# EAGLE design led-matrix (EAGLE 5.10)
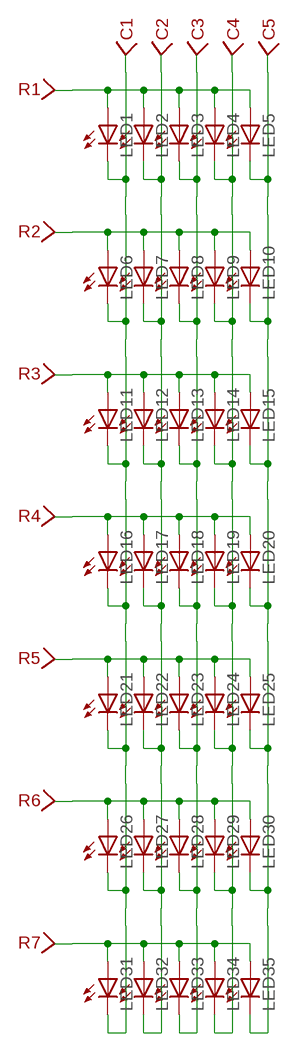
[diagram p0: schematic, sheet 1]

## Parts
C1  WIREPAD-SMD-SMALL-NAMED  [WIREPAD-SMD-SMALL]
C2  WIREPAD-SMD-SMALL-NAMED  [WIREPAD-SMD-SMALL]
C3  WIREPAD-SMD-SMALL-NAMED  [WIREPAD-SMD-SMALL]
C4  WIREPAD-SMD-SMALL-NAMED  [WIREPAD-SMD-SMALL]
C5  WIREPAD-SMD-SMALL-NAMED  [WIREPAD-SMD-SMALL]
LED1  LEDCHIPLED_0805  [CHIPLED_0805]
LED2  LEDCHIPLED_0805  [CHIPLED_0805]
LED3  LEDCHIPLED_0805  [CHIPLED_0805]
LED4  LEDCHIPLED_0805  [CHIPLED_0805]
LED5  LEDCHIPLED_0805  [CHIPLED_0805]
LED6  LEDCHIPLED_0805  [CHIPLED_0805]
LED7  LEDCHIPLED_0805  [CHIPLED_0805]
LED8  LEDCHIPLED_0805  [CHIPLED_0805]
LED9  LEDCHIPLED_0805  [CHIPLED_0805]
LED10  LEDCHIPLED_0805  [CHIPLED_0805]
LED11  LEDCHIPLED_0805  [CHIPLED_0805]
LED12  LEDCHIPLED_0805  [CHIPLED_0805]
LED13  LEDCHIPLED_0805  [CHIPLED_0805]
LED14  LEDCHIPLED_0805  [CHIPLED_0805]
LED15  LEDCHIPLED_0805  [CHIPLED_0805]
LED16  LEDCHIPLED_0805  [CHIPLED_0805]
LED17  LEDCHIPLED_0805  [CHIPLED_0805]
LED18  LEDCHIPLED_0805  [CHIPLED_0805]
LED19  LEDCHIPLED_0805  [CHIPLED_0805]
LED20  LEDCHIPLED_0805  [CHIPLED_0805]
LED21  LEDCHIPLED_0805  [CHIPLED_0805]
LED22  LEDCHIPLED_0805  [CHIPLED_0805]
LED23  LEDCHIPLED_0805  [CHIPLED_0805]
LED24  LEDCHIPLED_0805  [CHIPLED_0805]
LED25  LEDCHIPLED_0805  [CHIPLED_0805]
LED26  LEDCHIPLED_0805  [CHIPLED_0805]
LED27  LEDCHIPLED_0805  [CHIPLED_0805]
LED28  LEDCHIPLED_0805  [CHIPLED_0805]
LED29  LEDCHIPLED_0805  [CHIPLED_0805]
LED30  LEDCHIPLED_0805  [CHIPLED_0805]
LED31  LEDCHIPLED_0805  [CHIPLED_0805]
LED32  LEDCHIPLED_0805  [CHIPLED_0805]
LED33  LEDCHIPLED_0805  [CHIPLED_0805]
LED34  LEDCHIPLED_0805  [CHIPLED_0805]
LED35  LEDCHIPLED_0805  [CHIPLED_0805]
R1  WIREPAD-SMD-SMALL-NAMED  [WIREPAD-SMD-SMALL]
R2  WIREPAD-SMD-SMALL-NAMED  [WIREPAD-SMD-SMALL]
R3  WIREPAD-SMD-SMALL-NAMED  [WIREPAD-SMD-SMALL]
R4  WIREPAD-SMD-SMALL-NAMED  [WIREPAD-SMD-SMALL]
R5  WIREPAD-SMD-SMALL-NAMED  [WIREPAD-SMD-SMALL]
R6  WIREPAD-SMD-SMALL-NAMED  [WIREPAD-SMD-SMALL]
R7  WIREPAD-SMD-SMALL-NAMED  [WIREPAD-SMD-SMALL]

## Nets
A1: LED6.A LED7.A LED8.A LED9.A LED10.A R2.1
A2: LED11.A LED12.A LED13.A LED14.A LED15.A R3.1
A3: LED16.A LED17.A LED18.A LED19.A LED20.A R4.1
A4: LED1.A LED2.A LED3.A LED4.A LED5.A R1.1
A5: LED21.A LED22.A LED23.A LED24.A LED25.A R5.1
A6: LED26.A LED27.A LED28.A LED29.A LED30.A R6.1
A7: LED31.A LED32.A LED33.A LED34.A LED35.A R7.1
C7: C5.1 LED5.C LED10.C LED15.C LED20.C LED25.C LED30.C LED35.C
N$25: C1.1 LED1.C LED6.C LED11.C LED16.C LED21.C LED26.C LED31.C
N$26: C2.1 LED2.C LED7.C LED12.C LED17.C LED22.C LED27.C LED32.C
N$27: C3.1 LED3.C LED8.C LED13.C LED18.C LED23.C LED28.C LED33.C
N$28: C4.1 LED4.C LED9.C LED14.C LED19.C LED24.C LED29.C LED34.C

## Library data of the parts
C1-C5 R1-R7 = trl:WIREPAD-SMD-SMALL-NAMED
LED1-LED35 = led:LED: LED

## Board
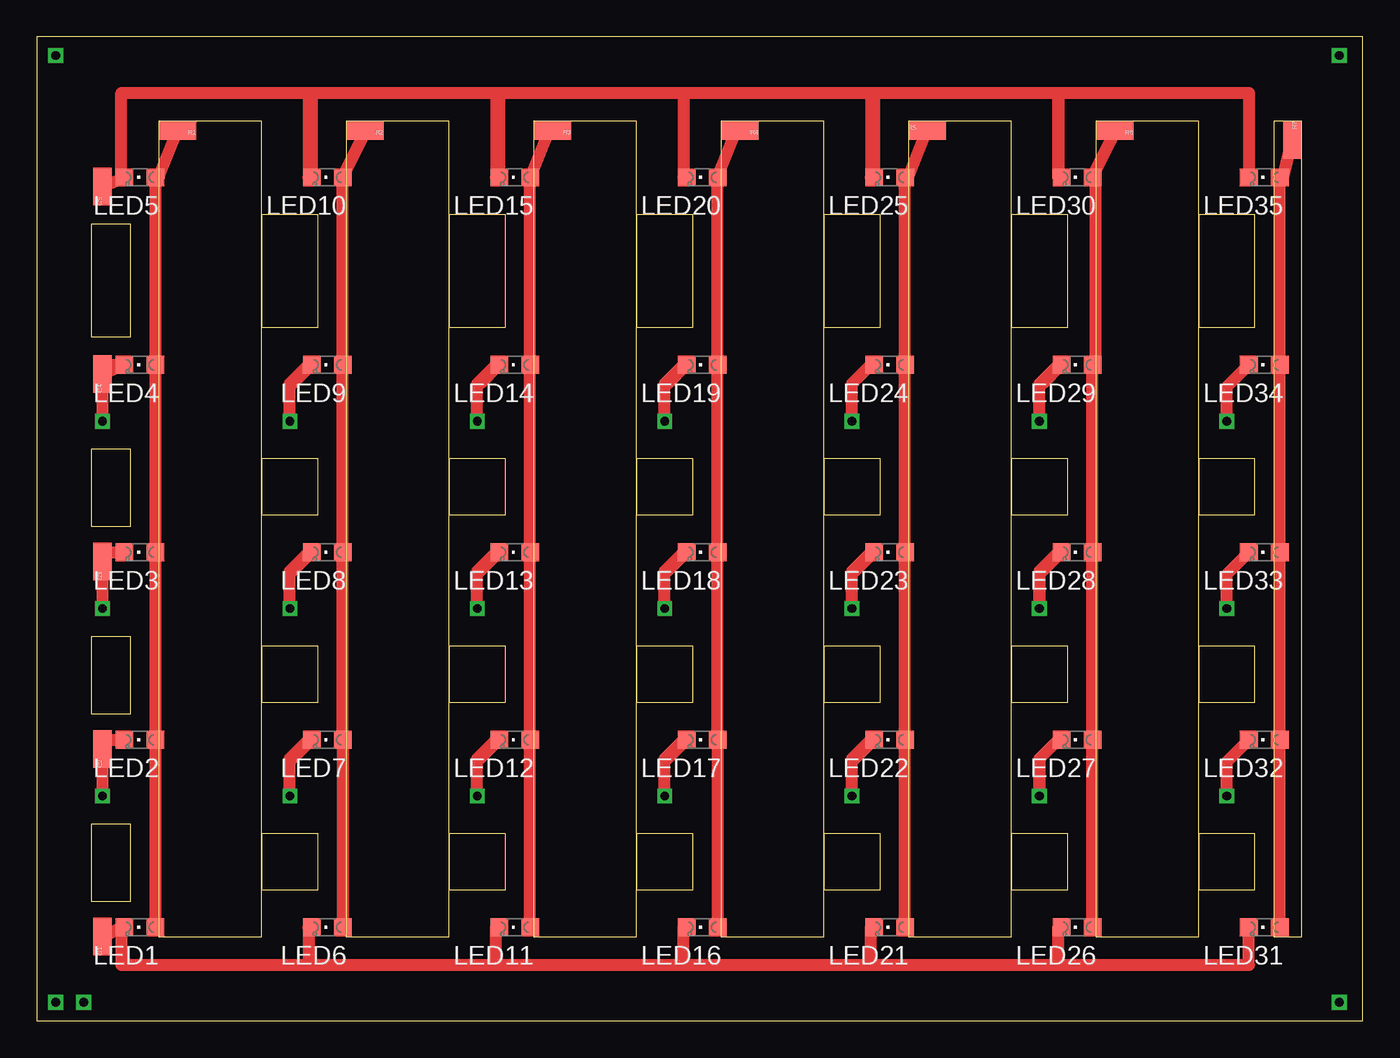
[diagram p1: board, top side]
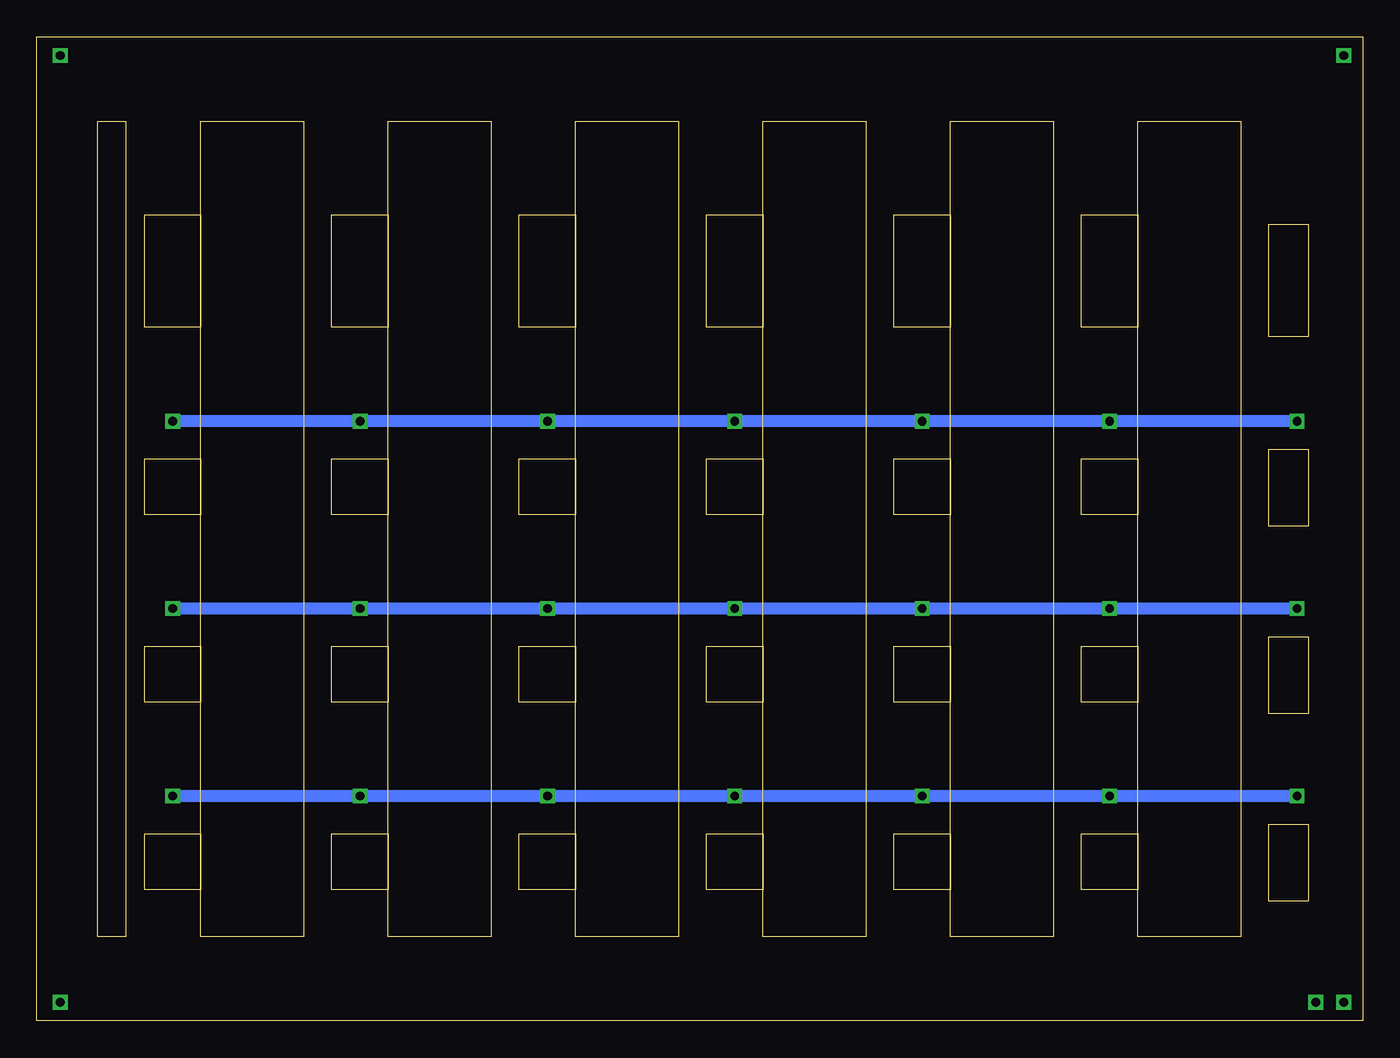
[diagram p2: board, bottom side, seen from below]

Size 89.84 x 66.67 mm. Coordinates in mm from the lower left corner, seen from the top.
Outline: 0,0 89.84,0 89.84,66.67 0,66.67 0,0
Copper layers (1*16): Top 0.035mm / dielectric 1.5mm / Bottom 0.035mm
Design rules "default": minimum track width 10mil, minimum drill 24mil, track to track 8mil, track to pad 8mil, pad to pad 8mil, via to via 8mil, smd to smd 8mil, copper to edge 40mil, drill to drill 8mil, minimum pad ring 10mil, minimum via ring 8mil, stop-mask expansion 4mil, vias tented up to drill 0mil, thermal gap 10mil
Milling: area 8.3,5.7 to 15.2,61; area 21,5.7 to 27.9,61; area 33.7,5.7 to 40.6,61; area 46.4,5.7 to 53.3,61; area 59.1,5.7 to 66,61; area 71.8,5.7 to 78.7,61; area 15.2,47 to 19.1,54.6; area 27.9,47 to 31.8,54.6; area 40.6,47 to 44.5,54.6; area 53.3,47 to 57.2,54.6; area 66,47 to 69.8,54.6; area 78.7,47 to 82.5,54.6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

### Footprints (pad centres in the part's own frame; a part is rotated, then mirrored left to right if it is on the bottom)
WIREPAD-SMD-SMALL = smd 2.54 x 1.27: 1 0,0
CHIPLED_0805 = smd 1.2 x 1.2: A 0,-1.05; C 0,1.05

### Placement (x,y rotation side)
C1  4.45,5.71 90 top
C2  4.45,18.41 90 top
C3  4.45,31.11 90 top
C4  4.45,43.81 90 top
C5  4.45,56.52 90 top
LED1  6.99,6.35 90 top
LED2  6.99,19.05 90 top
LED3  6.99,31.75 90 top
LED4  6.99,44.45 90 top
LED5  6.99,57.15 90 top
LED6  19.68,6.35 90 top
LED7  19.68,19.05 90 top
LED8  19.68,31.75 90 top
LED9  19.68,44.45 90 top
LED10  19.68,57.15 90 top
LED11  32.38,6.35 90 top
LED12  32.38,19.05 90 top
LED13  32.38,31.75 90 top
LED14  32.38,44.45 90 top
LED15  32.38,57.15 90 top
LED16  45.09,6.35 90 top
LED17  45.09,19.05 90 top
LED18  45.09,31.75 90 top
LED19  45.09,44.45 90 top
LED20  45.09,57.15 90 top
LED21  57.78,6.35 90 top
LED22  57.78,19.05 90 top
LED23  57.78,31.75 90 top
LED24  57.78,44.45 90 top
LED25  57.78,57.15 90 top
LED26  70.48,6.35 90 top
LED27  70.48,19.05 90 top
LED28  70.48,31.75 90 top
LED29  70.48,44.45 90 top
LED30  70.48,57.15 90 top
LED31  83.19,6.35 90 top
LED32  83.19,19.05 90 top
LED33  83.19,31.75 90 top
LED34  83.19,44.45 90 top
LED35  83.19,57.15 90 top
R1  9.53,60.33 180 top
R2  22.23,60.33 180 top
R3  34.92,60.33 180 top
R4  47.62,60.33 180 top
R5  60.33,60.33 0 top
R6  73.03,60.33 180 top
R7  85.09,59.69 270 top

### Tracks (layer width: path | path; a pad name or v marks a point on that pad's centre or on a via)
A1
  Top 0.813: R2.1 22,59.69 LED10.A LED9.A LED8.A LED7.A LED6.A
A2
  Top 0.813: LED11.A LED12.A LED13.A LED14.A LED15.A 34.7,60.33 R3.1
A3
  Top 0.813: R4.1 47.41,60.33 LED20.A LED19.A LED18.A LED17.A LED16.A
A4
  Top 0.813: LED2.A LED1.A LED2.A | LED2.A LED3.A | LED3.A LED4.A | LED4.A LED5.A | LED3.A LED4.A | LED4.A LED5.A | LED5.A 8.26,57.15 R1.1
A5
  Top 0.813: LED21.A LED22.A LED23.A LED24.A LED25.A 59.05,57.15 R5.1
A6
  Top 0.813: R6.1 72.81,59.69 LED30.A 71.75,57.15 71.75,44.45 LED29.A LED28.A LED27.A LED26.A
A7
  Top 0.813: LED31.A LED32.A LED33.A LED34.A LED35.A 84.45,57.15 R7.1
C7
  Top 0.813: C5.1 LED5.C 5.71,57.15 5.71,62.87 18.41,62.87 | 18.41,62.87 18.64,62.87 LED10.C 18.41,57.15 18.41,62.87 | 18.41,62.87 31.11,62.87 | 31.11,62.87 31.34,62.87 LED15.C 31.11,57.15 31.11,62.87 | 31.11,62.87 43.81,62.87 | 43.81,62.87 43.81,57.15 | 43.81,57.15 LED20.C 43.81,57.15 | 43.81,62.87 43.81,57.15 | 43.81,62.87 56.52,62.87 | 56.52,62.87 56.73,62.87 LED25.C 56.52,57.15 56.52,62.87 | 56.52,62.87 69.22,62.87 | 69.22,62.87 69.22,57.15 | 69.22,57.15 LED30.C 69.22,57.15 | 69.22,57.15 69.22,62.87 | 69.22,62.87 82.14,62.87 LED35.C
N$1  (via drill 0.6)
  other vias: 1.27,65.41
N$2  (via drill 0.6)
  other vias: 1.27,1.27
N$3  (via drill 0.6)
  other vias: 3.17,1.27
N$4  (via drill 0.6)
  other vias: 88.27,1.27
N$5  (via drill 0.6)
  other vias: 88.27,65.41
N$25
  Top 0.813: 5.71,6.35 LED1.C 5.71,6.35 | C1.1 5.71,6.35 | 5.71,6.35 5.71,3.81 18.41,3.81 | 18.41,3.81 31.11,3.81 | 31.11,3.81 43.81,3.81 | 43.81,3.81 56.52,3.81 | 56.52,3.81 69.22,3.81 | 69.22,3.81 82.14,3.81 LED31.C | LED26.C 69.22,6.35 69.22,3.81 | LED21.C 56.52,6.35 56.52,3.81 | LED16.C 43.81,6.35 43.81,3.81 | LED11.C 31.11,6.35 31.11,5.08 31.11,3.81 | LED6.C 18.41,6.35 18.41,3.81
N$26  (via drill 0.6)
  Top 0.813: 4.45,19.05 C2.1 | 4.45,19.05 LED2.C 4.45,19.05 | v4.45,15.24 4.45,19.05 | 67.94,17.78 v67.94,15.24 67.94,17.78 | 67.94,17.78 69.22,19.05 | 69.22,19.05 LED27.C 69.22,19.05 | 69.22,19.05 67.94,17.78 | v80.64,15.24 80.64,17.56 LED32.C | v17.14,15.24 17.14,17.56 LED7.C 18.41,19.05 17.14,17.78 v17.14,15.24 | v29.84,15.24 29.84,17.56 LED12.C 31.11,19.05 29.84,17.78 v29.84,15.24 | v42.55,15.24 42.55,17.56 LED17.C 43.81,19.05 42.55,17.78 v42.55,15.24 | v55.24,15.24 55.24,17.56 LED22.C 56.52,19.05 55.24,17.78 v55.24,15.24
  Bottom 0.813: v4.45,15.24 v17.14,15.24 v29.84,15.24 v42.55,15.24 v55.24,15.24 v67.94,15.24 v80.64,15.24
N$27  (via drill 0.6)
  Top 0.813: 4.45,31.75 C3.1 | 4.45,31.75 LED3.C 4.45,31.75 | v4.45,27.94 4.45,31.75 | v80.64,27.94 80.64,30.26 LED33.C | v17.14,27.94 17.14,30.26 LED8.C 18.41,31.75 17.14,30.48 v17.14,27.94 | v29.84,27.94 29.84,30.26 LED13.C 31.11,31.75 29.84,30.48 v29.84,27.94 | v42.55,27.94 42.55,30.26 LED18.C 43.81,31.75 42.55,30.48 v42.55,27.94 | v55.24,27.94 55.24,30.26 LED23.C 56.52,31.75 55.24,30.48 v55.24,27.94 | v67.94,27.94 67.94,30.26 LED28.C 69.22,31.75 67.94,30.48 v67.94,27.94
  Bottom 0.813: v4.45,27.94 v17.14,27.94 v29.84,27.94 v42.55,27.94 v55.24,27.94 v67.94,27.94 v80.64,27.94
N$28  (via drill 0.6)
  Top 0.813: C4.1 LED4.C 4.45,44.45 v4.45,40.64 | 29.84,43.18 v29.84,40.64 29.84,43.18 | 29.84,43.18 30.07,43.18 LED14.C 31.11,44.45 29.84,43.18 | 42.55,43.18 v42.55,40.64 42.55,43.18 | 42.55,43.18 42.77,43.18 LED19.C 43.81,44.45 42.55,43.18 | 55.24,43.18 v55.24,40.64 55.24,43.18 | 55.24,43.18 56.52,44.45 | 56.52,44.45 LED24.C 56.52,44.45 | 55.24,43.18 56.52,44.45 | 67.94,43.18 v67.94,40.64 67.94,43.18 | 67.94,43.18 68.17,43.18 LED29.C 69.22,44.45 67.94,43.18 | v80.64,40.64 80.64,42.96 LED34.C | v17.14,40.64 17.14,42.96 LED9.C 18.41,44.45 17.14,43.18 v17.14,40.64
  Bottom 0.813: v4.45,40.64 v17.14,40.64 v29.84,40.64 v42.55,40.64 v55.24,40.64 v67.94,40.64 v80.64,40.64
